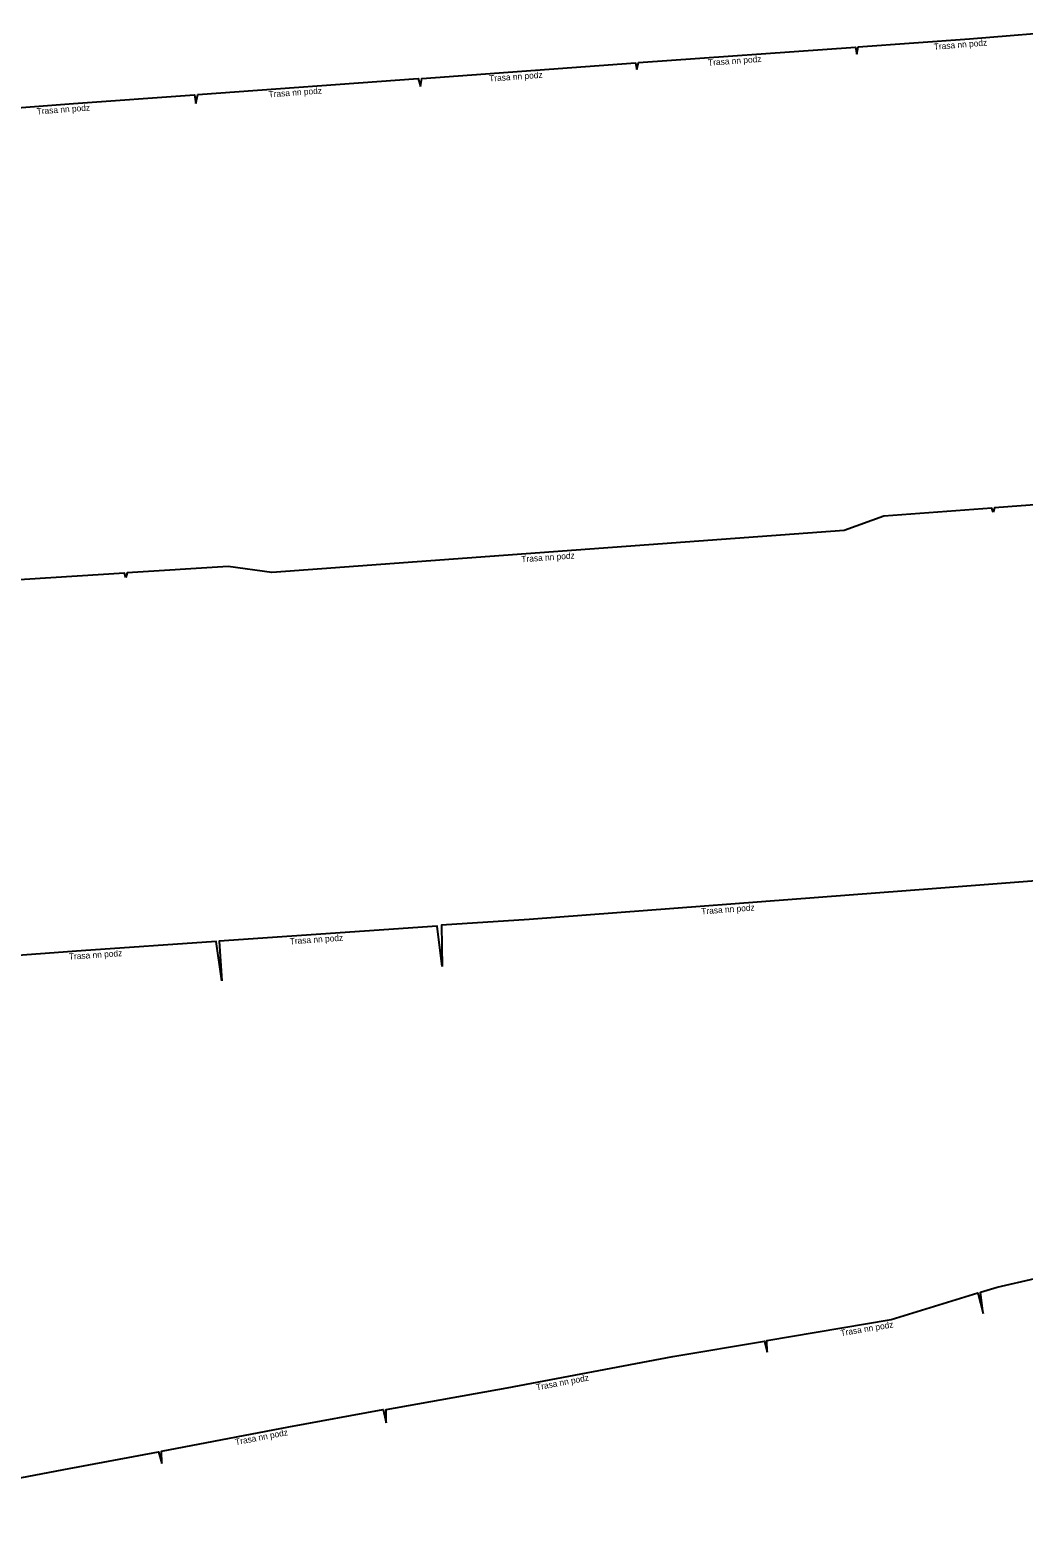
# Model space of a CAD drawing. Extents: x -873583 to -872966, y -1012951 to -1012536.
# Drawn here: x -873218 to -873138.5, y -1012741.8 to -1012621.3 of the extents above; entities that cross this region are included whole.
import ezdxf

# ---------------------------------------------------------------- set-up
doc = ezdxf.new("R2010")
doc.units = 0
doc.layers.add('Popiskový text - Ostatní atributy Trasy', color=7, linetype='Continuous')
doc.layers.add('Spojnice NN', color=7, linetype='Continuous')

msp = doc.modelspace()

# ---------------------------------------------------------------- linework, layer by layer
at = {"layer": 'Spojnice NN'}
for points in [[(-873151.88, -1012623.27), (-873151.77, -1012622.68), (-873142.88, -1012622.03), (-873134.44, -1012621.34), (-873134.23, -1012622.86)], [(-873169.46, -1012624.5), (-873169.34, -1012623.94), (-873152, -1012622.7), (-873151.88, -1012623.27)], [(-873186.76, -1012625.84), (-873186.65, -1012625.2), (-873169.58, -1012623.96), (-873169.46, -1012624.5)], [(-873204.71, -1012627.21), (-873204.55, -1012626.48), (-873186.93, -1012625.21), (-873186.76, -1012625.84)], [(-873223.22, -1012629.23), (-873223.15, -1012627.86), (-873214.48, -1012627.21), (-873204.82, -1012626.51), (-873204.71, -1012627.21)], [(-873123.31, -1012658.54), (-873123.44, -1012658.19), (-873140.89, -1012659.51), (-873140.99, -1012659.84)], [(-873140.99, -1012659.84), (-873141.1, -1012659.52), (-873149.72, -1012660.17), (-873152.91, -1012661.32), (-873198.64, -1012664.67), (-873202.13, -1012664.19), (-873210.21, -1012664.71), (-873210.31, -1012665.08)], [(-873210.31, -1012665.08), (-873210.42, -1012664.73), (-873220.08, -1012665.34), (-873228.71, -1012665.96), (-873228.78, -1012666.41)], [(-873136.85, -1012692.41), (-873137.2, -1012689.27), (-873147.95, -1012690.09), (-873178.06, -1012692.38), (-873185.09, -1012692.85), (-873185.02, -1012696.14)], [(-873185.02, -1012696.14), (-873185.42, -1012692.92), (-873202.85, -1012694.12), (-873202.63, -1012697.28)], [(-873202.63, -1012697.28), (-873203.08, -1012694.14), (-873213.88, -1012694.89), (-873220.41, -1012695.38), (-873220.36, -1012698.54)], [(-873141.79, -1012723.87), (-873142.01, -1012722.16), (-873140.68, -1012721.76), (-873131.65, -1012719.7), (-873130.22, -1012718.51), (-873129.11, -1012725.6), (-873130.17, -1012725.91), (-873130.47, -1012725.94)], [(-873159.06, -1012726.96), (-873159.07, -1012726.02), (-873149.15, -1012724.35), (-873142.21, -1012722.22), (-873141.79, -1012723.87)], [(-873189.51, -1012732.61), (-873189.51, -1012731.53), (-873179.84, -1012729.8), (-873166.59, -1012727.31), (-873159.28, -1012726.09), (-873159.06, -1012726.96)], [(-873207.42, -1012735.85), (-873207.45, -1012734.86), (-873197.28, -1012732.91), (-873189.73, -1012731.55), (-873189.51, -1012732.61)], [(-873237, -1012741.79), (-873237.07, -1012740.92), (-873229.81, -1012739.11), (-873215.26, -1012736.34), (-873207.69, -1012734.92), (-873207.42, -1012735.85)]]:
    msp.add_lwpolyline(points, dxfattribs=at)

# ---------------------------------------------------------------- texts
at = {"layer": 'Popiskový text - Ostatní atributy Trasy'}
for rotation, p in [(4.6538, (-873145.72, -1012622.92)), (4.1079, (-873163.76, -1012624.19)), (4.1494, (-873181.25, -1012625.46)), (4.1173, (-873198.88, -1012626.72)), (4.1863, (-873217.41, -1012628.08)), (4.1991, (-873178.68, -1012663.86)), (4.3471, (-873164.3, -1012691.99)), (3.9502, (-873197.19, -1012694.38)), (3.9554, (-873214.84, -1012695.61)), (9.5419, (-873153.15, -1012725.68)), (10.6291, (-873177.47, -1012730.01)), (10.8628, (-873201.52, -1012734.39))]:
    msp.add_text('Trasa nn podz', height=0.5, rotation=rotation, dxfattribs=at).set_placement(p)

doc.saveas('drawing.dxf')
